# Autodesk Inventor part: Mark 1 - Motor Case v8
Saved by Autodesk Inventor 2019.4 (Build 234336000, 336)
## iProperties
Created: 2020-06
Part Number: Mark 1 - Motor Case v8
Material: Generic
Document SubType Name: Modeling
Designer: Administrator
Density: 1 g/cm^3
Appearance: Default
Author: Administrator
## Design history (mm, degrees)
feature "Body2"
body "Solid1"
